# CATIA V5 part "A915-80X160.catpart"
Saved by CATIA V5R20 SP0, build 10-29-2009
Part number: A915-80X160
Source: Unknown
Property "A": "0.000"
Property "ARTICLENO": "A915-80X160"
Property "BOMINFO": "A915-80X160"
Property "CODE": "A915-80X160"
Property "CREATOR": "CADENAS GmbH"
Property "D": "13.500"
Property "D1": "20.000"
Property "FORM": "B"
Property "L": "160.000"
Property "L1": "25.000"
Property "L2": "110.000"
Property "LINA": "A915-80X160"
Property "NB": "A915-80X160"
Property "NBSYN": "$CODE."
Property "NN": "A915"
Property "NT": "VDI 3357 Wear Plates, steel"
Property "SCREW": "M12x25"
Property "SUPPLIER": "CF"
Property "T": "13.000"
Property "W": "80.000"
Bounding box of the stored display mesh (mm): x 0 to 20, y 0 to 160, z -40 to 40
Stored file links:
  C:\Users\borellobunino\Desktop\3D X SITO CF\A915\GSB_OILLESS_G22501080160\CATIAV5\A915-80X160.catpart
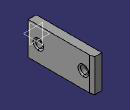
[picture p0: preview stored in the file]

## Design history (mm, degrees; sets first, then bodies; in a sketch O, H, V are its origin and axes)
Body1 "Geometry.1" (main body)
  Solid1 "A915-80X160.catpart": solid without history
